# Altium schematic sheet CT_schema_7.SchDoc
size 277 x 170 mm
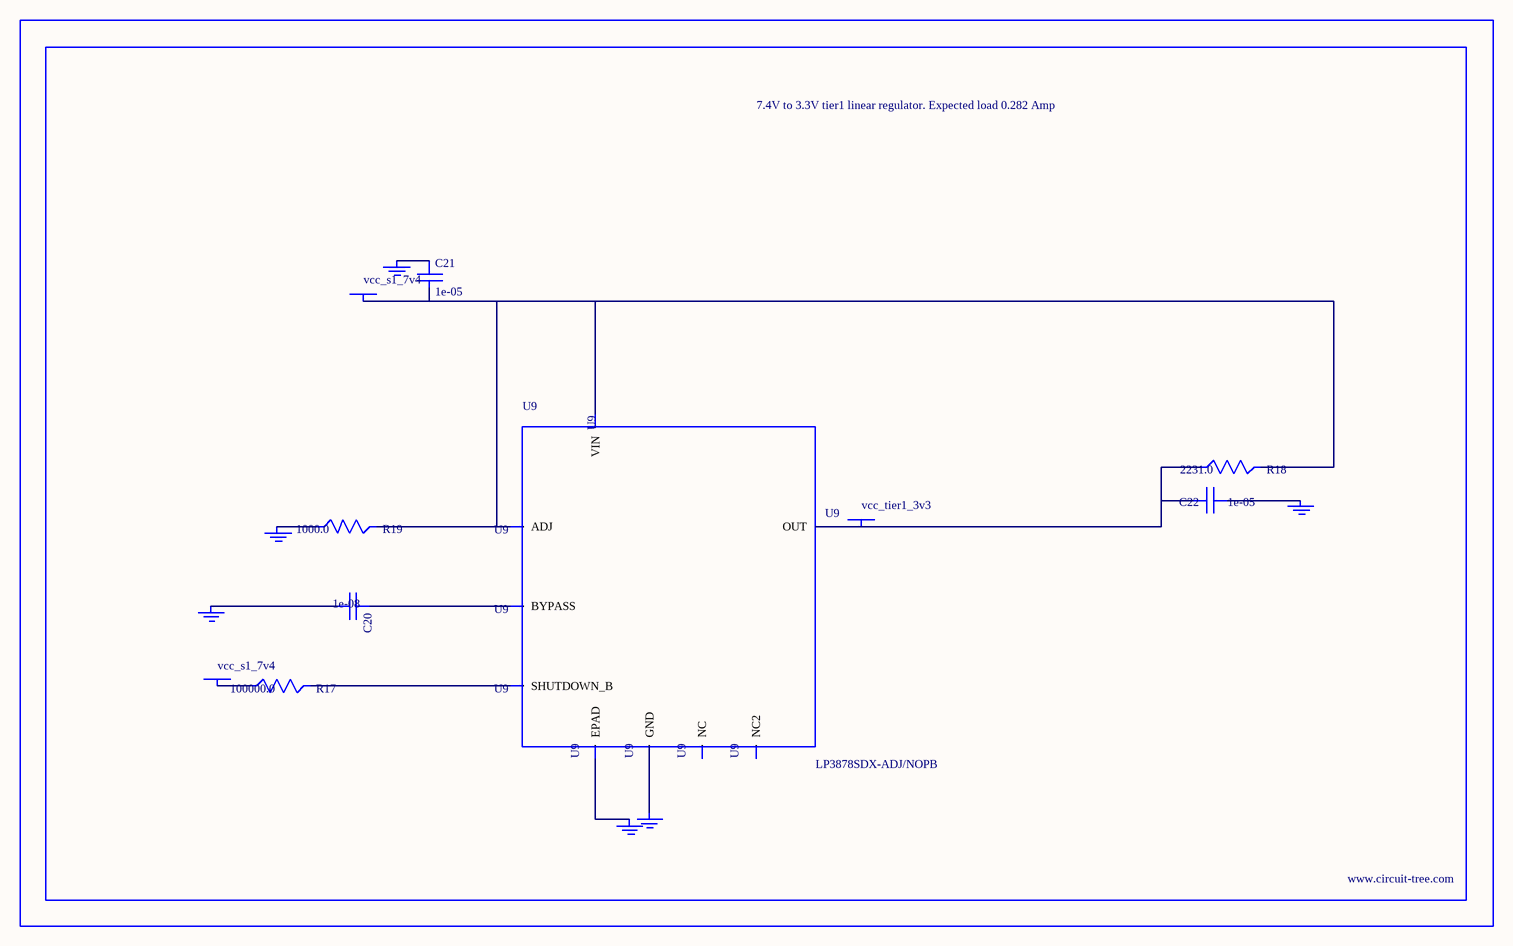
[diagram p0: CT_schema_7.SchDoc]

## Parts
BORDER6  (no value)
C20  1e-08  [C0402]
C21  1e-05  [C1206]
C22  1e-05  [C1210]
GND_INSTANCE_6_0  (no value)
GND_INSTANCE_6_1  (no value)
GND_INSTANCE_6_2  (no value)
GND_INSTANCE_6_3  (no value)
GND_INSTANCE_6_4  (no value)
GND_INSTANCE_6_5  (no value)
POWER_INSTANCE_6_0  vcc_s1_7v4
POWER_INSTANCE_6_1  vcc_s1_7v4
POWER_INSTANCE_6_2  vcc_tier1_3v3
R17  100000.0  [R0603]
R18  2231.0  [R0603]
R19  1000.0  [R0603]
U9  LP3878SDX-ADJ/NOPB  [WSON-8]

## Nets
NetC20_1: C20.1 U9.1(BYPASS)
NetC20_2: C20.2 GND_INSTANCE_6_0.0(GND)
NetC21_1: C21.1 GND_INSTANCE_6_1.0(GND)
NetC21_2: C21.2 POWER_INSTANCE_6_0.0(PWR) R18.2 R19.2 U9.4(VIN) U9.6(ADJ)
NetC22_1: C22.1 GND_INSTANCE_6_2.0(GND)
NetC22_2: C22.2 POWER_INSTANCE_6_2.0(PWR) R18.1 U9.5(OUT)
NetGND_INSTANCE_6_3_0: GND_INSTANCE_6_3.0(GND) R19.1
NetGND_INSTANCE_6_4_0: GND_INSTANCE_6_4.0(GND) U9.PAD(EPAD)
NetGND_INSTANCE_6_5_0: GND_INSTANCE_6_5.0(GND) U9.3(GND)
NetPOWER_INSTANCE_6_1_0: POWER_INSTANCE_6_1.0(PWR) R17.1
NetR17_2: R17.2 U9.8(SHUTDOWN_B)

Not connected (* = marked no-connect by the designer): U9 2(NC) 7(NC2)

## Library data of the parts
BORDER6 = BORDER_PAGE6
C20 = C0402C103K3RAC
C21 = C1206C106K3RACTU
C22 = GRM32DR61E106MA12L
GND_INSTANCE_6_0-GND_INSTANCE_6_5 = GND
POWER_INSTANCE_6_0-POWER_INSTANCE_6_2 = PWR
R17 = RC0603JR-07100KL
R18 = R18
R19 = RC0603JR-071KL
